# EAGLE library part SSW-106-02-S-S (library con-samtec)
THROUGH-HOLE .025" SQ POST SOCKET Source: Samtec SSW.pdf
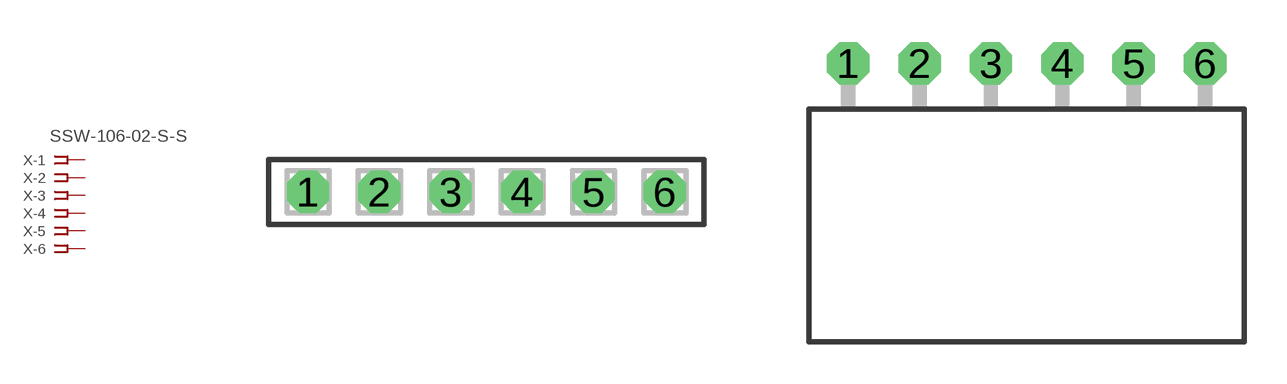
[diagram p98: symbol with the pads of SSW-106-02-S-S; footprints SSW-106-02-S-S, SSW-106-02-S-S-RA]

Designator prefix X; gates -1=FPINV -2=FPIN -3=FPIN -4=FPIN -5=FPIN -6=FPIN

## SSW-106-02-S-S (MPN: SSW-106-02-S-S; OC_FARNELL: unknown; OC_NEWARK: 11P9416)  [SSW-106-02-S-S]
1  -1:1  pas
2  -2:1  pas
3  -3:1  pas
4  -4:1  pas
5  -5:1  pas
6  -6:1  pas

## SSW-106-02-S-S-RA (MPN: SSW-106-02-S-S-RA; OC_FARNELL: unknown; OC_NEWARK: 11P9417)  [SSW-106-02-S-S-RA]
Pads as for SSW-106-02-S-S

## Footprint SSW-106-02-S-S (pad centres in mm)
THROUGH-HOLE .025" SQ POST SOCKET Source: Samtec SSW.pdf
drill 1 pad 1.5 octagon: 1 -6.35,0; 2 -3.81,0; 3 -1.27,0; 4 1.27,0; 5 3.81,0; 6 6.35,0

## Footprint SSW-106-02-S-S-RA (pad centres in mm)
THROUGH-HOLE .025" SQ POST SOCKET Source: Samtec SSW.pdf
drill 1 pad 1.5 octagon: 1 -6.35,1.524; 2 -3.81,1.524; 3 -1.27,1.524; 4 1.27,1.524; 5 3.81,1.524; 6 6.35,1.524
